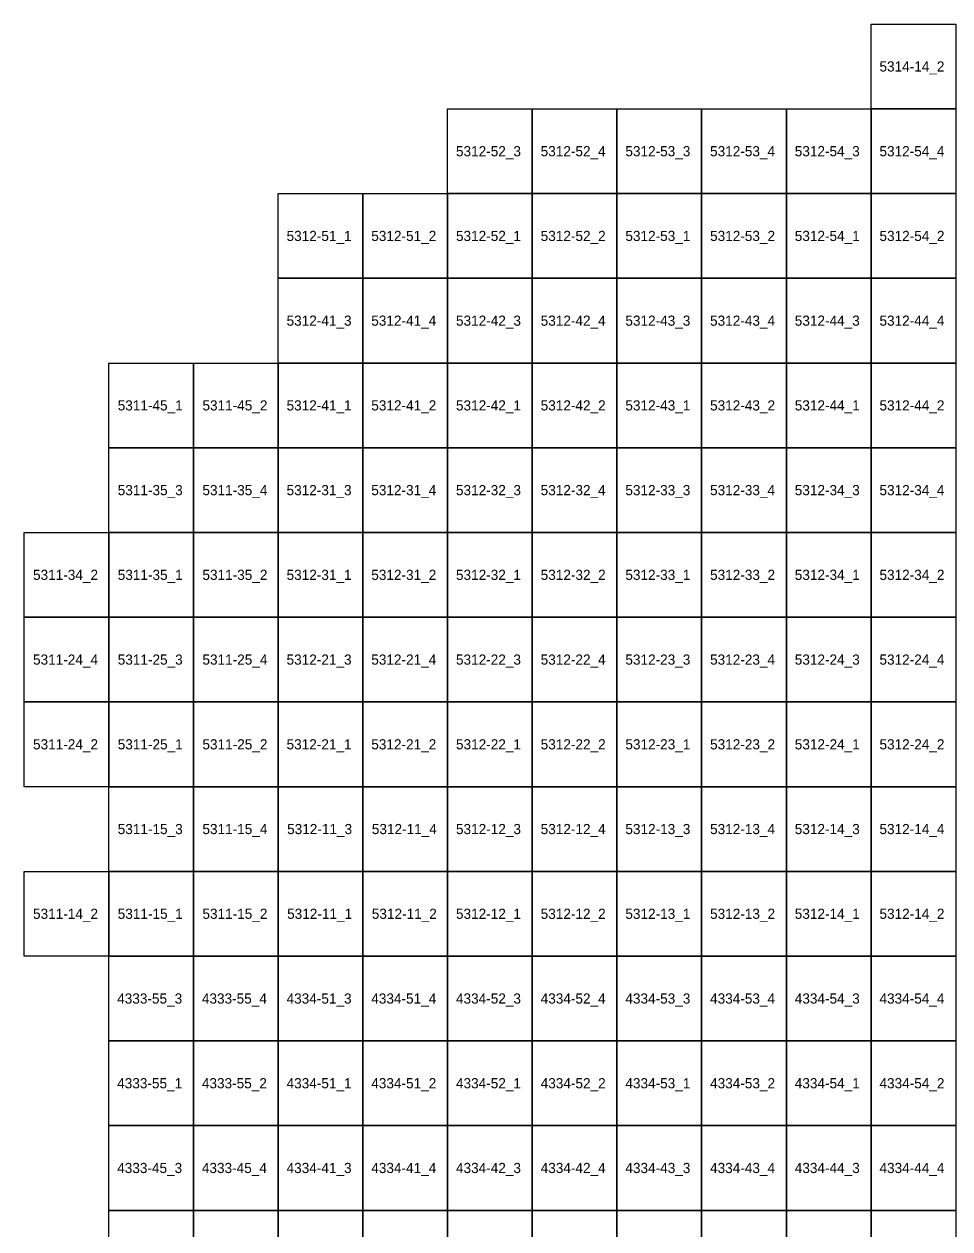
# Model space of a CAD drawing. Extents: x 312500 to 765000, y 172500 to 440000.
# Drawn here: x 517500 to 544827, y 391952 to 427500 of the extents above; entities that cross this region are included whole.
import ezdxf

# ---------------------------------------------------------------- set-up
doc = ezdxf.new("R2010")
doc.units = 0
doc.layers.add('Topo5_ramis_TKS2025', color=7, linetype='Continuous')
doc.layers.add('Topo5_ramis_TKS2025_Nr', color=7, linetype='Continuous')

msp = doc.modelspace()

# ---------------------------------------------------------------- linework, layer by layer
at = {"layer": 'Topo5_ramis_TKS2025'}
for points in [[(542500, 425000), (542500, 427500), (545000, 427500), (545000, 425000), (542500, 425000)], [(530000, 422500), (530000, 425000), (532500, 425000), (532500, 422500), (530000, 422500)], [(532500, 422500), (532500, 425000), (535000, 425000), (535000, 422500), (532500, 422500)], [(535000, 422500), (535000, 425000), (537500, 425000), (537500, 422500), (535000, 422500)], [(537500, 422500), (537500, 425000), (540000, 425000), (540000, 422500), (537500, 422500)], [(540000, 422500), (540000, 425000), (542500, 425000), (542500, 422500), (540000, 422500)], [(542500, 422500), (542500, 425000), (545000, 425000), (545000, 422500), (542500, 422500)], [(525000, 420000), (525000, 422500), (527500, 422500), (527500, 420000), (525000, 420000)], [(527500, 420000), (527500, 422500), (530000, 422500), (530000, 420000), (527500, 420000)], [(530000, 420000), (530000, 422500), (532500, 422500), (532500, 420000), (530000, 420000)], [(532500, 420000), (532500, 422500), (535000, 422500), (535000, 420000), (532500, 420000)], [(535000, 420000), (535000, 422500), (537500, 422500), (537500, 420000), (535000, 420000)], [(537500, 420000), (537500, 422500), (540000, 422500), (540000, 420000), (537500, 420000)], [(540000, 420000), (540000, 422500), (542500, 422500), (542500, 420000), (540000, 420000)], [(542500, 420000), (542500, 422500), (545000, 422500), (545000, 420000), (542500, 420000)], [(525000, 417500), (525000, 420000), (527500, 420000), (527500, 417500), (525000, 417500)], [(527500, 417500), (527500, 420000), (530000, 420000), (530000, 417500), (527500, 417500)], [(530000, 417500), (530000, 420000), (532500, 420000), (532500, 417500), (530000, 417500)], [(532500, 417500), (532500, 420000), (535000, 420000), (535000, 417500), (532500, 417500)], [(535000, 417500), (535000, 420000), (537500, 420000), (537500, 417500), (535000, 417500)], [(537500, 417500), (537500, 420000), (540000, 420000), (540000, 417500), (537500, 417500)], [(540000, 417500), (540000, 420000), (542500, 420000), (542500, 417500), (540000, 417500)], [(542500, 417500), (542500, 420000), (545000, 420000), (545000, 417500), (542500, 417500)], [(520000, 415000), (520000, 417500), (522500, 417500), (522500, 415000), (520000, 415000)], [(522500, 415000), (522500, 417500), (525000, 417500), (525000, 415000), (522500, 415000)], [(525000, 415000), (525000, 417500), (527500, 417500), (527500, 415000), (525000, 415000)], [(527500, 415000), (527500, 417500), (530000, 417500), (530000, 415000), (527500, 415000)], [(530000, 415000), (530000, 417500), (532500, 417500), (532500, 415000), (530000, 415000)], [(532500, 415000), (532500, 417500), (535000, 417500), (535000, 415000), (532500, 415000)], [(535000, 415000), (535000, 417500), (537500, 417500), (537500, 415000), (535000, 415000)], [(537500, 415000), (537500, 417500), (540000, 417500), (540000, 415000), (537500, 415000)], [(540000, 415000), (540000, 417500), (542500, 417500), (542500, 415000), (540000, 415000)], [(542500, 415000), (542500, 417500), (545000, 417500), (545000, 415000), (542500, 415000)], [(520000, 412500), (520000, 415000), (522500, 415000), (522500, 412500), (520000, 412500)], [(522500, 412500), (522500, 415000), (525000, 415000), (525000, 412500), (522500, 412500)], [(525000, 412500), (525000, 415000), (527500, 415000), (527500, 412500), (525000, 412500)], [(527500, 412500), (527500, 415000), (530000, 415000), (530000, 412500), (527500, 412500)], [(530000, 412500), (530000, 415000), (532500, 415000), (532500, 412500), (530000, 412500)], [(532500, 412500), (532500, 415000), (535000, 415000), (535000, 412500), (532500, 412500)], [(535000, 412500), (535000, 415000), (537500, 415000), (537500, 412500), (535000, 412500)], [(537500, 412500), (537500, 415000), (540000, 415000), (540000, 412500), (537500, 412500)], [(540000, 412500), (540000, 415000), (542500, 415000), (542500, 412500), (540000, 412500)], [(542500, 412500), (542500, 415000), (545000, 415000), (545000, 412500), (542500, 412500)], [(517500, 410000), (517500, 412500), (520000, 412500), (520000, 410000), (517500, 410000)], [(520000, 410000), (520000, 412500), (522500, 412500), (522500, 410000), (520000, 410000)], [(522500, 410000), (522500, 412500), (525000, 412500), (525000, 410000), (522500, 410000)], [(525000, 410000), (525000, 412500), (527500, 412500), (527500, 410000), (525000, 410000)], [(527500, 410000), (527500, 412500), (530000, 412500), (530000, 410000), (527500, 410000)], [(530000, 410000), (530000, 412500), (532500, 412500), (532500, 410000), (530000, 410000)], [(532500, 410000), (532500, 412500), (535000, 412500), (535000, 410000), (532500, 410000)], [(535000, 410000), (535000, 412500), (537500, 412500), (537500, 410000), (535000, 410000)], [(537500, 410000), (537500, 412500), (540000, 412500), (540000, 410000), (537500, 410000)], [(540000, 410000), (540000, 412500), (542500, 412500), (542500, 410000), (540000, 410000)], [(542500, 410000), (542500, 412500), (545000, 412500), (545000, 410000), (542500, 410000)], [(517500, 407500), (517500, 410000), (520000, 410000), (520000, 407500), (517500, 407500)], [(520000, 407500), (520000, 410000), (522500, 410000), (522500, 407500), (520000, 407500)], [(522500, 407500), (522500, 410000), (525000, 410000), (525000, 407500), (522500, 407500)], [(525000, 407500), (525000, 410000), (527500, 410000), (527500, 407500), (525000, 407500)], [(527500, 407500), (527500, 410000), (530000, 410000), (530000, 407500), (527500, 407500)], [(530000, 407500), (530000, 410000), (532500, 410000), (532500, 407500), (530000, 407500)], [(532500, 407500), (532500, 410000), (535000, 410000), (535000, 407500), (532500, 407500)], [(535000, 407500), (535000, 410000), (537500, 410000), (537500, 407500), (535000, 407500)], [(537500, 407500), (537500, 410000), (540000, 410000), (540000, 407500), (537500, 407500)], [(540000, 407500), (540000, 410000), (542500, 410000), (542500, 407500), (540000, 407500)], [(542500, 407500), (542500, 410000), (545000, 410000), (545000, 407500), (542500, 407500)], [(517500, 405000), (517500, 407500), (520000, 407500), (520000, 405000), (517500, 405000)], [(520000, 405000), (520000, 407500), (522500, 407500), (522500, 405000), (520000, 405000)], [(522500, 405000), (522500, 407500), (525000, 407500), (525000, 405000), (522500, 405000)], [(525000, 405000), (525000, 407500), (527500, 407500), (527500, 405000), (525000, 405000)], [(527500, 405000), (527500, 407500), (530000, 407500), (530000, 405000), (527500, 405000)], [(530000, 405000), (530000, 407500), (532500, 407500), (532500, 405000), (530000, 405000)], [(532500, 405000), (532500, 407500), (535000, 407500), (535000, 405000), (532500, 405000)], [(535000, 405000), (535000, 407500), (537500, 407500), (537500, 405000), (535000, 405000)], [(537500, 405000), (537500, 407500), (540000, 407500), (540000, 405000), (537500, 405000)], [(540000, 405000), (540000, 407500), (542500, 407500), (542500, 405000), (540000, 405000)], [(542500, 405000), (542500, 407500), (545000, 407500), (545000, 405000), (542500, 405000)], [(520000, 402500), (520000, 405000), (522500, 405000), (522500, 402500), (520000, 402500)], [(522500, 402500), (522500, 405000), (525000, 405000), (525000, 402500), (522500, 402500)], [(525000, 402500), (525000, 405000), (527500, 405000), (527500, 402500), (525000, 402500)], [(527500, 402500), (527500, 405000), (530000, 405000), (530000, 402500), (527500, 402500)], [(530000, 402500), (530000, 405000), (532500, 405000), (532500, 402500), (530000, 402500)], [(532500, 402500), (532500, 405000), (535000, 405000), (535000, 402500), (532500, 402500)], [(535000, 402500), (535000, 405000), (537500, 405000), (537500, 402500), (535000, 402500)], [(537500, 402500), (537500, 405000), (540000, 405000), (540000, 402500), (537500, 402500)], [(540000, 402500), (540000, 405000), (542500, 405000), (542500, 402500), (540000, 402500)], [(542500, 402500), (542500, 405000), (545000, 405000), (545000, 402500), (542500, 402500)], [(517500, 400000), (517500, 402500), (520000, 402500), (520000, 400000), (517500, 400000)], [(520000, 400000), (520000, 402500), (522500, 402500), (522500, 400000), (520000, 400000)], [(522500, 400000), (522500, 402500), (525000, 402500), (525000, 400000), (522500, 400000)], [(525000, 400000), (525000, 402500), (527500, 402500), (527500, 400000), (525000, 400000)], [(527500, 400000), (527500, 402500), (530000, 402500), (530000, 400000), (527500, 400000)], [(530000, 400000), (530000, 402500), (532500, 402500), (532500, 400000), (530000, 400000)], [(532500, 400000), (532500, 402500), (535000, 402500), (535000, 400000), (532500, 400000)], [(535000, 400000), (535000, 402500), (537500, 402500), (537500, 400000), (535000, 400000)], [(537500, 400000), (537500, 402500), (540000, 402500), (540000, 400000), (537500, 400000)], [(540000, 400000), (540000, 402500), (542500, 402500), (542500, 400000), (540000, 400000)], [(542500, 400000), (542500, 402500), (545000, 402500), (545000, 400000), (542500, 400000)], [(520000, 397500), (520000, 400000), (522500, 400000), (522500, 397500), (520000, 397500)], [(522500, 397500), (522500, 400000), (525000, 400000), (525000, 397500), (522500, 397500)], [(525000, 397500), (525000, 400000), (527500, 400000), (527500, 397500), (525000, 397500)], [(527500, 397500), (527500, 400000), (530000, 400000), (530000, 397500), (527500, 397500)], [(530000, 397500), (530000, 400000), (532500, 400000), (532500, 397500), (530000, 397500)], [(532500, 397500), (532500, 400000), (535000, 400000), (535000, 397500), (532500, 397500)], [(535000, 397500), (535000, 400000), (537500, 400000), (537500, 397500), (535000, 397500)], [(537500, 397500), (537500, 400000), (540000, 400000), (540000, 397500), (537500, 397500)], [(540000, 397500), (540000, 400000), (542500, 400000), (542500, 397500), (540000, 397500)], [(542500, 397500), (542500, 400000), (545000, 400000), (545000, 397500), (542500, 397500)], [(520000, 395000), (520000, 397500), (522500, 397500), (522500, 395000), (520000, 395000)], [(522500, 395000), (522500, 397500), (525000, 397500), (525000, 395000), (522500, 395000)], [(525000, 395000), (525000, 397500), (527500, 397500), (527500, 395000), (525000, 395000)], [(527500, 395000), (527500, 397500), (530000, 397500), (530000, 395000), (527500, 395000)], [(530000, 395000), (530000, 397500), (532500, 397500), (532500, 395000), (530000, 395000)], [(532500, 395000), (532500, 397500), (535000, 397500), (535000, 395000), (532500, 395000)], [(535000, 395000), (535000, 397500), (537500, 397500), (537500, 395000), (535000, 395000)], [(537500, 395000), (537500, 397500), (540000, 397500), (540000, 395000), (537500, 395000)], [(540000, 395000), (540000, 397500), (542500, 397500), (542500, 395000), (540000, 395000)], [(542500, 395000), (542500, 397500), (545000, 397500), (545000, 395000), (542500, 395000)], [(520000, 392500), (520000, 395000), (522500, 395000), (522500, 392500), (520000, 392500)], [(522500, 392500), (522500, 395000), (525000, 395000), (525000, 392500), (522500, 392500)], [(525000, 392500), (525000, 395000), (527500, 395000), (527500, 392500), (525000, 392500)], [(527500, 392500), (527500, 395000), (530000, 395000), (530000, 392500), (527500, 392500)], [(530000, 392500), (530000, 395000), (532500, 395000), (532500, 392500), (530000, 392500)], [(532500, 392500), (532500, 395000), (535000, 395000), (535000, 392500), (532500, 392500)], [(535000, 392500), (535000, 395000), (537500, 395000), (537500, 392500), (535000, 392500)], [(537500, 392500), (537500, 395000), (540000, 395000), (540000, 392500), (537500, 392500)], [(540000, 392500), (540000, 395000), (542500, 395000), (542500, 392500), (540000, 392500)], [(542500, 392500), (542500, 395000), (545000, 395000), (545000, 392500), (542500, 392500)], [(520000, 390000), (520000, 392500), (522500, 392500), (522500, 390000), (520000, 390000)], [(522500, 390000), (522500, 392500), (525000, 392500), (525000, 390000), (522500, 390000)], [(525000, 390000), (525000, 392500), (527500, 392500), (527500, 390000), (525000, 390000)], [(527500, 390000), (527500, 392500), (530000, 392500), (530000, 390000), (527500, 390000)], [(530000, 390000), (530000, 392500), (532500, 392500), (532500, 390000), (530000, 390000)], [(532500, 390000), (532500, 392500), (535000, 392500), (535000, 390000), (532500, 390000)], [(535000, 390000), (535000, 392500), (537500, 392500), (537500, 390000), (535000, 390000)], [(537500, 390000), (537500, 392500), (540000, 392500), (540000, 390000), (537500, 390000)], [(540000, 390000), (540000, 392500), (542500, 392500), (542500, 390000), (540000, 390000)], [(542500, 390000), (542500, 392500), (545000, 392500), (545000, 390000), (542500, 390000)]]:
    msp.add_lwpolyline(points, dxfattribs=at)

# ---------------------------------------------------------------- texts
at = {"layer": 'Topo5_ramis_TKS2025_Nr'}
for s, p in [('5314-14_2', (542748, 426100)), ('5312-52_3', (530248, 423600)), ('5312-52_4', (532748, 423600)), ('5312-53_3', (535248, 423600)), ('5312-53_4', (537748, 423600)), ('5312-54_3', (540248, 423600)), ('5312-54_4', (542748, 423600)), ('5312-51_1', (525248, 421100)), ('5312-51_2', (527748, 421100)), ('5312-52_1', (530248, 421100)), ('5312-52_2', (532748, 421100)), ('5312-53_1', (535248, 421100)), ('5312-53_2', (537748, 421100)), ('5312-54_1', (540248, 421100)), ('5312-54_2', (542748, 421100)), ('5312-41_3', (525248, 418600)), ('5312-41_4', (527748, 418600)), ('5312-42_3', (530248, 418600)), ('5312-42_4', (532748, 418600)), ('5312-43_3', (535248, 418600)), ('5312-43_4', (537748, 418600)), ('5312-44_3', (540248, 418600)), ('5312-44_4', (542748, 418600)), ('5311-45_1', (520264, 416100)), ('5311-45_2', (522764, 416100)), ('5312-41_1', (525248, 416100)), ('5312-41_2', (527748, 416100)), ('5312-42_1', (530248, 416100)), ('5312-42_2', (532748, 416100)), ('5312-43_1', (535248, 416100)), ('5312-43_2', (537748, 416100)), ('5312-44_1', (540248, 416100)), ('5312-44_2', (542748, 416100)), ('5311-35_3', (520264, 413600)), ('5311-35_4', (522764, 413600)), ('5312-31_3', (525248, 413600)), ('5312-31_4', (527748, 413600)), ('5312-32_3', (530248, 413600)), ('5312-32_4', (532748, 413600)), ('5312-33_3', (535248, 413600)), ('5312-33_4', (537748, 413600)), ('5312-34_3', (540248, 413600)), ('5312-34_4', (542748, 413600)), ('5311-34_2', (517764, 411100)), ('5311-35_1', (520264, 411100)), ('5311-35_2', (522764, 411100)), ('5312-31_1', (525248, 411100)), ('5312-31_2', (527748, 411100)), ('5312-32_1', (530248, 411100)), ('5312-32_2', (532748, 411100)), ('5312-33_1', (535248, 411100)), ('5312-33_2', (537748, 411100)), ('5312-34_1', (540248, 411100)), ('5312-34_2', (542748, 411100)), ('5311-24_4', (517764, 408600)), ('5311-25_3', (520264, 408600)), ('5311-25_4', (522764, 408600)), ('5312-21_3', (525248, 408600)), ('5312-21_4', (527748, 408600)), ('5312-22_3', (530248, 408600)), ('5312-22_4', (532748, 408600)), ('5312-23_3', (535248, 408600)), ('5312-23_4', (537748, 408600)), ('5312-24_3', (540248, 408600)), ('5312-24_4', (542748, 408600)), ('5311-24_2', (517764, 406100)), ('5311-25_1', (520264, 406100)), ('5311-25_2', (522764, 406100)), ('5312-21_1', (525248, 406100)), ('5312-21_2', (527748, 406100)), ('5312-22_1', (530248, 406100)), ('5312-22_2', (532748, 406100)), ('5312-23_1', (535248, 406100)), ('5312-23_2', (537748, 406100)), ('5312-24_1', (540248, 406100)), ('5312-24_2', (542748, 406100)), ('5311-15_3', (520264, 403600)), ('5311-15_4', (522764, 403600)), ('5312-11_3', (525264, 403600)), ('5312-11_4', (527764, 403600)), ('5312-12_3', (530248, 403600)), ('5312-12_4', (532748, 403600)), ('5312-13_3', (535248, 403600)), ('5312-13_4', (537748, 403600)), ('5312-14_3', (540248, 403600)), ('5312-14_4', (542748, 403600)), ('5311-14_2', (517764, 401100)), ('5311-15_1', (520264, 401100)), ('5311-15_2', (522764, 401100)), ('5312-11_1', (525264, 401100)), ('5312-11_2', (527764, 401100)), ('5312-12_1', (530248, 401100)), ('5312-12_2', (532748, 401100)), ('5312-13_1', (535248, 401100)), ('5312-13_2', (537748, 401100)), ('5312-14_1', (540248, 401100)), ('5312-14_2', (542748, 401100)), ('4333-55_3', (520248, 398600)), ('4333-55_4', (522748, 398600)), ('4334-51_3', (525248, 398600)), ('4334-51_4', (527748, 398600)), ('4334-52_3', (530248, 398600)), ('4334-52_4', (532748, 398600)), ('4334-53_3', (535248, 398600)), ('4334-53_4', (537748, 398600)), ('4334-54_3', (540248, 398600)), ('4334-54_4', (542748, 398600)), ('4333-55_1', (520248, 396100)), ('4333-55_2', (522748, 396100)), ('4334-51_1', (525248, 396100)), ('4334-51_2', (527748, 396100)), ('4334-52_1', (530248, 396100)), ('4334-52_2', (532748, 396100)), ('4334-53_1', (535248, 396100)), ('4334-53_2', (537748, 396100)), ('4334-54_1', (540248, 396100)), ('4334-54_2', (542748, 396100)), ('4333-45_3', (520248, 393600)), ('4333-45_4', (522748, 393600)), ('4334-41_3', (525248, 393600)), ('4334-41_4', (527748, 393600)), ('4334-42_3', (530248, 393600)), ('4334-42_4', (532748, 393600)), ('4334-43_3', (535248, 393600)), ('4334-43_4', (537748, 393600)), ('4334-44_3', (540248, 393600)), ('4334-44_4', (542748, 393600))]:
    msp.add_text(s, height=300, dxfattribs=at).set_placement(p)

doc.saveas('drawing.dxf')
